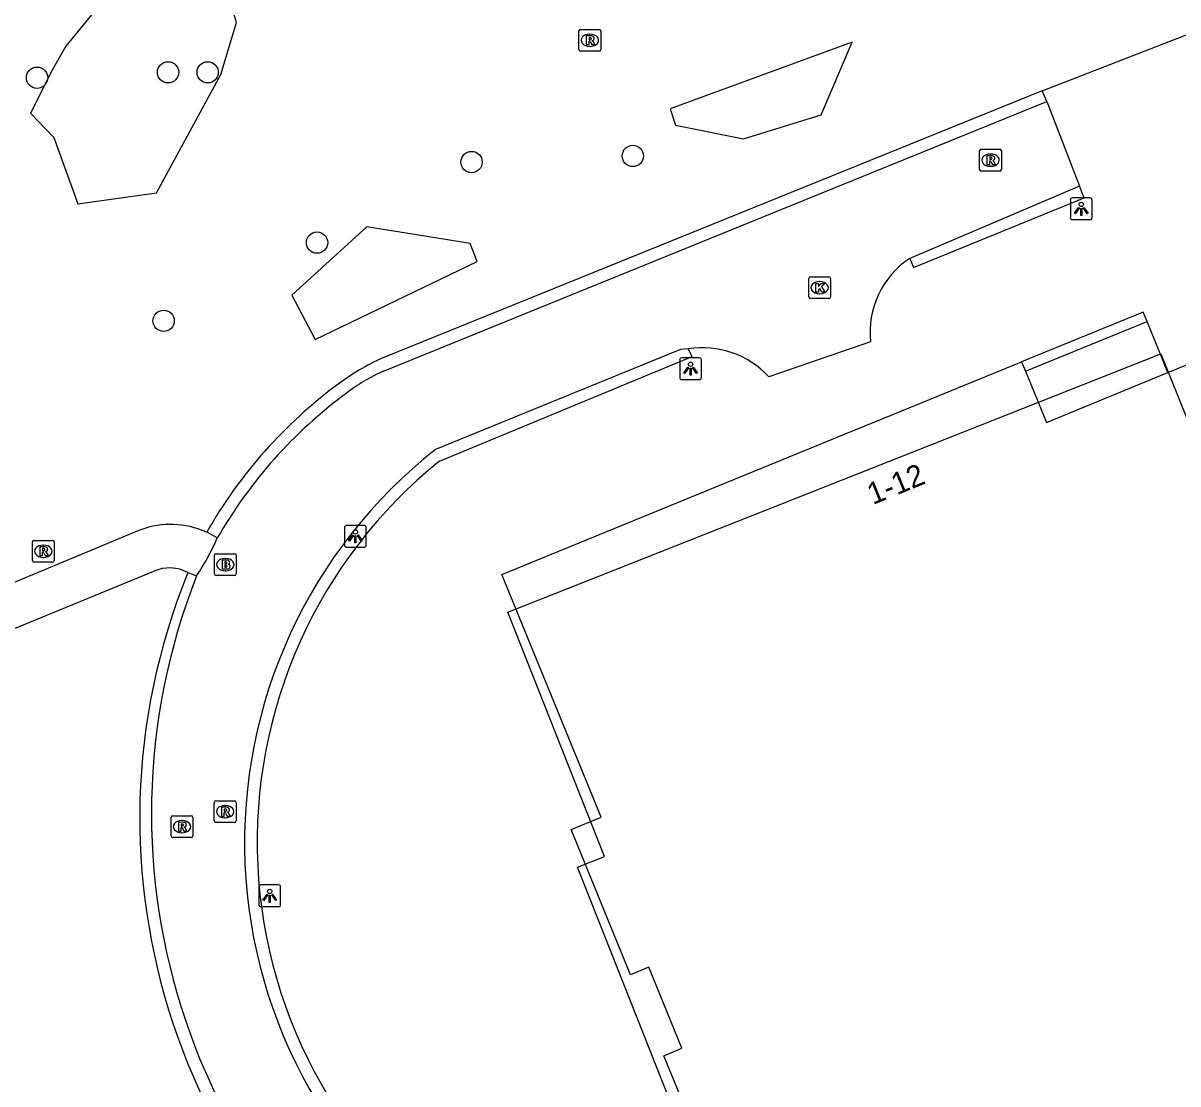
# Model space of a CAD drawing. Extents: x 156664 to 157568, y 383571 to 384421.
# Drawn here: x 156758.2 to 156811.2, y 383832.6 to 383881.2 of the extents above; entities that cross this region are included whole.
import ezdxf

# ---------------------------------------------------------------- set-up
doc = ezdxf.new("R2010")
doc.units = 0
for name, color, linetype in [('IMGEO_Boom', 7, 'Continuous'), ('IMGEO_Brandkraan', 7, 'Continuous'), ('IMGEO_Groenvoorziening', 7, 'Continuous'), ('IMGEO_Kolk', 7, 'Continuous'), ('IMGEO_Lichtpunt', 7, 'Continuous'), ('IMGEO_Muur', 7, 'Continuous'), ('IMGEO_Pand', 7, 'Continuous'), ('IMGEO_Pand_nummerreeks', 7, 'Continuous'), ('IMGEO_Pand_vergunning_verleend', 7, 'Continuous'), ('IMGEO_Rijbaan_lokaal_gesloten', 7, 'Continuous'), ('IMGEO_Rijbaan_lokaal_open', 7, 'Continuous'), ('IMGEO_Rioolput', 7, 'Continuous'), ('IMGEO_Voetpad_halfverhard', 7, 'Continuous'), ('IMGEO_Voetpad_op_trap', 7, 'Continuous')]:
    doc.layers.add(name, color=color, linetype=linetype)

msp = doc.modelspace()

# ---------------------------------------------------------------- linework, layer by layer
at = {"layer": 'IMGEO_Boom'}
for centre in [(156758.877, 383878.729), (156764.888, 383878.978), (156766.703, 383878.978), (156786.206, 383875.144), (156778.807, 383874.862), (156771.719, 383871.166), (156764.683, 383867.578)]:
    msp.add_circle(centre, 0.489, dxfattribs=at)
at = {"layer": 'IMGEO_Brandkraan'}
for p, q in [((156767.014, 383855.969), (156767.014, 383856.821)), ((156767.089, 383856.895), (156767.941, 383856.895)), ((156767.502, 383856.675), (156767.527, 383856.675)), ((156768.015, 383856.821), (156768.015, 383855.969)), ((156767.941, 383855.895), (156767.089, 383855.895)), ((156767.525, 383856.115), (156767.5, 383856.115))]:
    msp.add_line(p, q, dxfattribs=at)
for points in [[(156767.014, 383855.969), (156767.014, 383856.821)], [(156767.089, 383856.895), (156767.941, 383856.895)], [(156767.362, 383856.595), (156767.362, 383856.195), (156767.575, 383856.195)], [(156767.593, 383856.595), (156767.362, 383856.595)], [(156767.541, 383856.514), (156767.487, 383856.514), (156767.487, 383856.438)], [(156767.487, 383856.438), (156767.54, 383856.438)], [(156768.015, 383856.821), (156768.015, 383855.969)], [(156767.941, 383855.895), (156767.089, 383855.895)], [(156767.549, 383856.362), (156767.487, 383856.362), (156767.487, 383856.281)], [(156767.487, 383856.281), (156767.549, 383856.281)]]:
    msp.add_lwpolyline(points, dxfattribs=at)
for centre, radius, start, end in [((156767.091, 383856.819), 0.0765, 91.552, 178.448), ((156767.091, 383856.819), 0.0765, 91.552, 178.448), ((156767.542, 383856.476), 0.0379, 267.8285, 90.9355), ((156767.597, 383856.45), 0.145, 59.4692, 91.5367), ((156767.622, 383856.497), 0.0922, 285.5137, 58.1501), ((156767.627, 383856.305), 0.105, 301.3115, 78.989), ((156767.939, 383856.819), 0.0765, 1.552, 88.448), ((156767.939, 383856.819), 0.0765, 1.552, 88.448), ((156767.091, 383855.971), 0.0765, 181.552, 268.448), ((156767.091, 383855.971), 0.0765, 181.552, 268.448), ((156767.55, 383856.321), 0.0404, 269.8759, 90.5077), ((156767.581, 383856.446), 0.251, 268.6676, 293.5347), ((156767.939, 383855.971), 0.0765, 271.552, 358.448), ((156767.939, 383855.971), 0.0765, 271.552, 358.448)]:
    msp.add_arc(centre, radius, start, end, dxfattribs=at)
for centre, major_axis, ratio, start_param, end_param in [((156767.501, 383856.395), (-0.387, 0.002), 0.722429, 4.712389, 7.853982), ((156767.526, 383856.395), (-0.39, 0.002), 0.717154, 1.570796, 4.712389)]:
    msp.add_ellipse(centre, major_axis=major_axis, ratio=ratio, start_param=start_param, end_param=end_param, dxfattribs=at)
at = {"layer": 'IMGEO_Groenvoorziening'}
for points in [[(156767.313, 383878.874), (156768.021, 383881.267), (156767.299, 383883.721), (156765.415, 383884.973), (156763.24, 383883.907), (156760.194, 383880.185), (156759.562, 383879.076), (156758.573, 383877.099), (156759.648, 383875.982), (156760.744, 383872.951), (156764.354, 383873.446), (156767.313, 383878.874)], [(156804.978, 383878.126), (156811.831, 383880.795)], [(156787.923, 383877.302), (156788.163, 383876.561), (156791.276, 383875.93), (156794.852, 383877.022), (156796.266, 383880.363), (156787.923, 383877.302)], [(156779.059, 383870.302), (156778.739, 383871.124), (156773.998, 383871.897), (156770.569, 383868.754), (156771.64, 383866.725), (156779.059, 383870.302)]]:
    msp.add_lwpolyline(points, dxfattribs=at)
at = {"layer": 'IMGEO_Kolk'}
for p, q in [((156794.276, 383868.672), (156794.276, 383869.524)), ((156794.351, 383869.598), (156795.203, 383869.598)), ((156794.764, 383869.378), (156794.789, 383869.378)), ((156795.277, 383869.524), (156795.277, 383868.672)), ((156795.203, 383868.598), (156794.351, 383868.598)), ((156794.787, 383868.818), (156794.762, 383868.818))]:
    msp.add_line(p, q, dxfattribs=at)
for points in [[(156794.276, 383868.672), (156794.276, 383869.524)], [(156794.351, 383869.598), (156795.203, 383869.598)], [(156794.597, 383869.298), (156794.72, 383869.298), (156794.72, 383869.147), (156794.85, 383869.298), (156795.014, 383869.298), (156794.868, 383869.147), (156795.021, 383868.898), (156794.869, 383868.898), (156794.784, 383869.062), (156794.72, 383868.995), (156794.72, 383868.898), (156794.597, 383868.898), (156794.597, 383869.298)], [(156795.277, 383869.524), (156795.277, 383868.672)], [(156795.203, 383868.598), (156794.351, 383868.598)]]:
    msp.add_lwpolyline(points, dxfattribs=at)
for centre, start, end in [((156794.353, 383869.522), 91.552, 178.448), ((156794.353, 383869.522), 91.552, 178.448), ((156795.201, 383869.522), 1.552, 88.448), ((156795.201, 383869.522), 1.552, 88.448), ((156794.353, 383868.674), 181.552, 268.448), ((156794.353, 383868.674), 181.552, 268.448), ((156795.201, 383868.674), 271.552, 358.448), ((156795.201, 383868.674), 271.552, 358.448)]:
    msp.add_arc(centre, 0.0765, start, end, dxfattribs=at)
for centre, major_axis, ratio, start_param, end_param in [((156794.763, 383869.098), (-0.387, 0.002), 0.722429, 4.712389, 7.853982), ((156794.788, 383869.098), (-0.39, 0.002), 0.717154, 1.570796, 4.712389)]:
    msp.add_ellipse(centre, major_axis=major_axis, ratio=ratio, start_param=start_param, end_param=end_param, dxfattribs=at)
at = {"layer": 'IMGEO_Lichtpunt'}
for p, q in [((156806.276, 383873.12), (156806.276, 383872.313)), ((156806.276, 383873.12), (156806.276, 383872.313)), ((156807.178, 383873.215), (156806.37, 383873.215)), ((156807.178, 383873.215), (156806.37, 383873.215)), ((156807.272, 383872.313), (156807.272, 383873.12)), ((156807.272, 383872.313), (156807.272, 383873.12)), ((156806.37, 383872.219), (156807.178, 383872.219)), ((156806.37, 383872.219), (156807.178, 383872.219)), ((156788.355, 383865.785), (156788.355, 383864.978)), ((156788.355, 383865.785), (156788.355, 383864.978)), ((156789.257, 383865.88), (156788.449, 383865.88)), ((156789.257, 383865.88), (156788.449, 383865.88)), ((156789.351, 383864.978), (156789.351, 383865.785)), ((156789.351, 383864.978), (156789.351, 383865.785)), ((156788.449, 383864.884), (156789.257, 383864.884)), ((156788.449, 383864.884), (156789.257, 383864.884)), ((156772.98, 383858.094), (156772.98, 383857.287)), ((156772.98, 383858.094), (156772.98, 383857.287)), ((156773.882, 383858.189), (156773.074, 383858.189)), ((156773.882, 383858.189), (156773.074, 383858.189)), ((156773.976, 383857.287), (156773.976, 383858.094)), ((156773.976, 383857.287), (156773.976, 383858.094)), ((156773.074, 383857.193), (156773.882, 383857.193)), ((156773.074, 383857.193), (156773.882, 383857.193)), ((156769.054, 383841.606), (156769.054, 383840.799)), ((156769.054, 383841.606), (156769.054, 383840.799)), ((156769.956, 383841.701), (156769.148, 383841.701)), ((156769.956, 383841.701), (156769.148, 383841.701)), ((156770.05, 383840.799), (156770.05, 383841.606)), ((156770.05, 383840.799), (156770.05, 383841.606)), ((156769.148, 383840.705), (156769.956, 383840.705)), ((156769.148, 383840.705), (156769.956, 383840.705))]:
    msp.add_line(p, q, dxfattribs=at)
for points in [[(156806.65, 383872.784), (156806.689, 383872.756), (156806.501, 383872.494), (156806.463, 383872.521), (156806.65, 383872.784)], [(156806.752, 383872.736), (156806.799, 383872.736), (156806.799, 383872.414), (156806.752, 383872.414), (156806.752, 383872.736)], [(156806.862, 383872.756), (156806.9, 383872.783), (156807.087, 383872.521), (156807.048, 383872.493), (156806.862, 383872.756)], [(156788.729, 383865.449), (156788.768, 383865.421), (156788.58, 383865.159), (156788.542, 383865.186), (156788.729, 383865.449)], [(156788.941, 383865.421), (156788.979, 383865.448), (156789.166, 383865.186), (156789.127, 383865.158), (156788.941, 383865.421)], [(156788.831, 383865.401), (156788.878, 383865.401), (156788.878, 383865.079), (156788.831, 383865.079), (156788.831, 383865.401)], [(156773.354, 383857.758), (156773.393, 383857.73), (156773.205, 383857.468), (156773.167, 383857.495), (156773.354, 383857.758)], [(156773.456, 383857.71), (156773.503, 383857.71), (156773.503, 383857.388), (156773.456, 383857.388), (156773.456, 383857.71)], [(156773.566, 383857.73), (156773.604, 383857.757), (156773.791, 383857.495), (156773.752, 383857.467), (156773.566, 383857.73)], [(156769.428, 383841.27), (156769.467, 383841.242), (156769.279, 383840.98), (156769.241, 383841.007), (156769.428, 383841.27)], [(156769.53, 383841.222), (156769.577, 383841.222), (156769.577, 383840.9), (156769.53, 383840.9), (156769.53, 383841.222)], [(156769.64, 383841.242), (156769.678, 383841.269), (156769.865, 383841.007), (156769.826, 383840.979), (156769.64, 383841.242)]]:
    msp.add_lwpolyline(points, dxfattribs=at)
for centre in [(156806.775, 383872.918), (156788.854, 383865.583), (156773.479, 383857.892), (156769.553, 383841.404)]:
    msp.add_circle(centre, 0.0994, dxfattribs=at)
for centre, start, end in [((156806.37, 383873.12), 90, 180), ((156806.37, 383873.12), 90, 180), ((156807.178, 383873.12), 0, 90), ((156807.178, 383873.12), 0, 90), ((156806.37, 383872.313), 180, 270), ((156806.37, 383872.313), 180, 270), ((156807.178, 383872.313), 270, 0), ((156807.178, 383872.313), 270, 360), ((156788.449, 383865.785), 90, 180), ((156788.449, 383865.785), 90, 180), ((156789.257, 383865.785), 0, 90), ((156789.257, 383865.785), 0, 90), ((156788.449, 383864.978), 180, 270), ((156788.449, 383864.978), 180, 270), ((156789.257, 383864.978), 270, 0), ((156789.257, 383864.978), 270, 360), ((156773.074, 383858.094), 90, 180), ((156773.074, 383858.094), 90, 180), ((156773.882, 383858.094), 0, 90), ((156773.882, 383858.094), 0, 90), ((156773.074, 383857.287), 180, 270), ((156773.074, 383857.287), 180, 270), ((156773.882, 383857.287), 270, 0), ((156773.882, 383857.287), 270, 360), ((156769.148, 383841.606), 90, 180), ((156769.148, 383841.606), 90, 180), ((156769.956, 383841.606), 0, 90), ((156769.956, 383841.606), 0, 90), ((156769.148, 383840.799), 180, 270), ((156769.148, 383840.799), 180, 270), ((156769.956, 383840.799), 270, 0), ((156769.956, 383840.799), 270, 360)]:
    msp.add_arc(centre, 0.0946, start, end, dxfattribs=at)
at = {"layer": 'IMGEO_Muur'}
for points in [[(156809.794, 383867.543), (156809.615, 383867.977), (156804.039, 383865.696)], [(156804.217, 383865.261), (156809.794, 383867.543)]]:
    msp.add_lwpolyline(points, dxfattribs=at)
at = {"layer": 'IMGEO_Pand'}
for points in [[(156807.966, 383825.04), (156808.116, 383824.67), (156800.741, 383821.682), (156799.598, 383824.496), (156795.415, 383822.785), (156793.137, 383828.33), (156790.362, 383827.188), (156787.627, 383833.862), (156788.459, 383834.206), (156786.933, 383837.925), (156786.103, 383837.581), (156783.375, 383844.241), (156784.761, 383844.813), (156780.2, 383855.943), (156794.056, 383861.612), (156795.923, 383862.376), (156798.209, 383863.311), (156804.039, 383865.696)], [(156804.039, 383865.696), (156804.217, 383865.261)], [(156810.752, 383865.212), (156812.318, 383865.856), (156814.59, 383860.304), (156817.377, 383861.45), (156822.064, 383849.936), (156821.462, 383849.689), (156823.742, 383844.139), (156820.198, 383842.684), (156822.503, 383837.144), (156816.871, 383834.832), (156818.054, 383832.045), (156811.056, 383829.074)], [(156804.217, 383865.261), (156805.179, 383862.921), (156810.752, 383865.212)]]:
    msp.add_lwpolyline(points, dxfattribs=at)
at = {"layer": 'IMGEO_Pand_vergunning_verleend'}
msp.add_lwpolyline([(156780.469, 383854.207), (156810.422, 383866.069), (156813.706, 383857.943), (156816.747, 383859.147), (156823.563, 383841.936), (156820.432, 383840.696), (156822.305, 383835.967), (156820.454, 383835.234), (156822.799, 383829.314), (156801.042, 383820.698), (156799.834, 383823.747), (156795.744, 383822.127), (156793.475, 383827.857), (156790.011, 383826.485), (156783.663, 383842.517), (156784.904, 383843.008), (156780.469, 383854.207)], dxfattribs=at)
at = {"layer": 'IMGEO_Rijbaan_lokaal_gesloten'}
for points in [[(156804.978, 383878.126), (156774.705, 383865.868)], [(156805.203, 383877.639), (156804.978, 383878.126)], [(156774.773, 383865.272), (156805.203, 383877.639)], [(156806.698, 383873.755), (156798.908, 383870.442)], [(156798.908, 383870.442), (156799.086, 383870.018), (156806.905, 383873.221), (156806.698, 383873.755)], [(156788.751, 383866.299), (156788.39, 383866.267), (156777.151, 383861.675)], [(156777.333, 383861.139), (156788.93, 383865.945), (156788.751, 383866.299)], [(156767.144, 383857.616), (156766.659, 383857.882)], [(156765.799, 383856.03), (156766.195, 383855.876)]]:
    msp.add_lwpolyline(points, dxfattribs=at)
for centre, radius, start, end in [((156779.457, 383855.553), 11.357, 114.7348, 126.5541), ((156778.442, 383857.162), 8.902, 114.3401, 127.2638), ((156785.762, 383846.992), 21.989, 126.4662, 150.3149), ((156785.971, 383846.787), 21.719, 126.4993, 150.0922), ((156791.351, 383843.635), 22.958, 128.2084, 236.6145), ((156791.42, 383843.662), 22.447, 128.8708, 236.5377), ((156793.467, 383844.757), 29.876, 157.8328, 238.869), ((156793.864, 383844.982), 29.736, 158.5089, 238.5458)]:
    msp.add_arc(centre, radius, start, end, dxfattribs=at)
at = {"layer": 'IMGEO_Rijbaan_lokaal_open'}
for points in [[(156805.203, 383877.639), (156806.698, 383873.755)], [(156797.106, 383866.622), (156792.449, 383865.012)]]:
    msp.add_lwpolyline(points, dxfattribs=at)
for centre, radius, start, end in [((156801.172, 383867.039), 4.087, 123.636, 185.8549), ((156789.388, 383862.174), 4.174, 42.8376, 98.784), ((156755.707, 383862.725), 12.526, 326.8542, 335.9295)]:
    msp.add_arc(centre, radius, start, end, dxfattribs=at)
at = {"layer": 'IMGEO_Rioolput'}
for p, q in [((156783.736, 383880.023), (156783.736, 383880.875)), ((156783.811, 383880.949), (156784.663, 383880.949)), ((156784.737, 383880.875), (156784.737, 383880.023)), ((156784.224, 383880.729), (156784.249, 383880.729)), ((156784.663, 383879.949), (156783.811, 383879.949)), ((156784.247, 383880.169), (156784.222, 383880.169)), ((156802.115, 383874.524), (156802.115, 383875.376)), ((156802.19, 383875.45), (156803.042, 383875.45)), ((156802.603, 383875.23), (156802.628, 383875.23)), ((156803.116, 383875.376), (156803.116, 383874.524)), ((156803.042, 383874.45), (156802.19, 383874.45)), ((156802.626, 383874.67), (156802.601, 383874.67)), ((156758.74, 383857.507), (156759.592, 383857.507)), ((156758.665, 383856.581), (156758.665, 383857.433)), ((156759.153, 383857.287), (156759.178, 383857.287)), ((156759.666, 383857.433), (156759.666, 383856.581)), ((156759.592, 383856.507), (156758.74, 383856.507)), ((156759.176, 383856.727), (156759.151, 383856.727)), ((156767.006, 383844.635), (156767.006, 383845.487)), ((156767.081, 383845.561), (156767.933, 383845.561)), ((156767.494, 383845.341), (156767.519, 383845.341)), ((156768.007, 383845.487), (156768.007, 383844.635)), ((156765.024, 383843.946), (156765.024, 383844.798)), ((156765.099, 383844.872), (156765.951, 383844.872)), ((156766.025, 383844.798), (156766.025, 383843.946)), ((156767.517, 383844.781), (156767.492, 383844.781)), ((156765.512, 383844.652), (156765.537, 383844.652)), ((156767.933, 383844.561), (156767.081, 383844.561)), ((156765.951, 383843.872), (156765.099, 383843.872)), ((156765.535, 383844.092), (156765.51, 383844.092))]:
    msp.add_line(p, q, dxfattribs=at)
for points in [[(156783.736, 383880.023), (156783.736, 383880.875)], [(156783.811, 383880.949), (156784.663, 383880.949)], [(156784.737, 383880.875), (156784.737, 383880.023)], [(156784.325, 383880.647), (156784.073, 383880.649), (156784.073, 383880.249)], [(156784.073, 383880.249), (156784.197, 383880.249), (156784.197, 383880.411), (156784.208, 383880.411)], [(156784.251, 383880.568), (156784.197, 383880.568), (156784.197, 383880.487)], [(156784.197, 383880.487), (156784.249, 383880.487)], [(156784.255, 383880.382), (156784.326, 383880.249), (156784.466, 383880.249), (156784.401, 383880.375)], [(156784.663, 383879.949), (156783.811, 383879.949)], [(156802.115, 383874.524), (156802.115, 383875.376)], [(156802.19, 383875.45), (156803.042, 383875.45)], [(156802.704, 383875.148), (156802.452, 383875.15), (156802.452, 383874.75)], [(156802.63, 383875.069), (156802.576, 383875.069), (156802.576, 383874.988)], [(156802.576, 383874.988), (156802.628, 383874.988)], [(156803.116, 383875.376), (156803.116, 383874.524)], [(156803.042, 383874.45), (156802.19, 383874.45)], [(156802.452, 383874.75), (156802.576, 383874.75), (156802.576, 383874.912), (156802.587, 383874.912)], [(156802.634, 383874.883), (156802.705, 383874.75), (156802.845, 383874.75), (156802.78, 383874.876)], [(156758.74, 383857.507), (156759.592, 383857.507)], [(156758.665, 383856.581), (156758.665, 383857.433)], [(156759.254, 383857.205), (156759.002, 383857.207), (156759.002, 383856.807)], [(156759.002, 383856.807), (156759.126, 383856.807), (156759.126, 383856.969), (156759.137, 383856.969)], [(156759.18, 383857.126), (156759.126, 383857.126), (156759.126, 383857.045)], [(156759.126, 383857.045), (156759.178, 383857.045)], [(156759.184, 383856.94), (156759.255, 383856.807), (156759.395, 383856.807), (156759.33, 383856.933)], [(156759.666, 383857.433), (156759.666, 383856.581)], [(156759.592, 383856.507), (156758.74, 383856.507)], [(156767.006, 383844.635), (156767.006, 383845.487)], [(156767.081, 383845.561), (156767.933, 383845.561)], [(156768.007, 383845.487), (156768.007, 383844.635)], [(156765.024, 383843.946), (156765.024, 383844.798)], [(156765.099, 383844.872), (156765.951, 383844.872)], [(156766.025, 383844.798), (156766.025, 383843.946)], [(156767.595, 383845.259), (156767.343, 383845.261), (156767.343, 383844.861)], [(156767.343, 383844.861), (156767.467, 383844.861), (156767.467, 383845.023), (156767.478, 383845.023)], [(156767.521, 383845.18), (156767.467, 383845.18), (156767.467, 383845.099)], [(156767.467, 383845.099), (156767.519, 383845.099)], [(156767.525, 383844.994), (156767.596, 383844.861), (156767.736, 383844.861), (156767.671, 383844.987)], [(156765.613, 383844.57), (156765.361, 383844.572), (156765.361, 383844.172)], [(156765.361, 383844.172), (156765.485, 383844.172), (156765.485, 383844.334), (156765.496, 383844.334)], [(156765.539, 383844.491), (156765.485, 383844.491), (156765.485, 383844.41)], [(156765.485, 383844.41), (156765.537, 383844.41)], [(156765.543, 383844.305), (156765.614, 383844.172), (156765.754, 383844.172), (156765.689, 383844.298)], [(156767.933, 383844.561), (156767.081, 383844.561)], [(156765.951, 383843.872), (156765.099, 383843.872)]]:
    msp.add_lwpolyline(points, dxfattribs=at)
for centre, radius, start, end in [((156783.813, 383880.873), 0.0765, 91.552, 178.448), ((156783.813, 383880.873), 0.0765, 91.552, 178.448), ((156784.661, 383880.873), 0.0765, 1.552, 88.448), ((156784.661, 383880.873), 0.0765, 1.552, 88.448), ((156784.207, 383880.358), 0.0533, 26.0293, 88.6989), ((156784.233, 383880.676), 0.19, 274.7715, 282.9687), ((156784.257, 383880.472), 0.0964, 77.0061, 93.1865), ((156784.271, 383880.529), 0.0378, 276.6634, 79.6772), ((156784.324, 383880.537), 0.109, 350.3612, 89.416), ((156784.322, 383880.537), 0.112, 277.5842, 350.9817), ((156784.306, 383880.322), 0.108, 29.5134, 73.7905), ((156783.813, 383880.025), 0.0765, 181.552, 268.448), ((156783.813, 383880.025), 0.0765, 181.552, 268.448), ((156784.661, 383880.025), 0.0765, 271.552, 358.448), ((156784.661, 383880.025), 0.0765, 271.552, 358.448), ((156802.192, 383875.374), 0.0765, 91.552, 178.448), ((156802.192, 383875.374), 0.0765, 91.552, 178.448), ((156802.612, 383875.177), 0.19, 274.7715, 282.9687), ((156802.636, 383874.973), 0.0964, 77.0061, 93.1865), ((156802.65, 383875.03), 0.0378, 276.6634, 79.6772), ((156802.703, 383875.038), 0.109, 350.3612, 89.416), ((156802.701, 383875.038), 0.112, 277.5842, 350.9817), ((156803.04, 383875.374), 0.0765, 1.552, 88.448), ((156803.04, 383875.374), 0.0765, 1.552, 88.448), ((156802.192, 383874.526), 0.0765, 181.552, 268.448), ((156802.192, 383874.526), 0.0765, 181.552, 268.448), ((156802.586, 383874.859), 0.0533, 26.0293, 88.6989), ((156802.685, 383874.823), 0.108, 29.5134, 73.7905), ((156803.04, 383874.526), 0.0765, 271.552, 358.448), ((156803.04, 383874.526), 0.0765, 271.552, 358.448), ((156758.742, 383857.431), 0.0765, 91.552, 178.448), ((156758.742, 383857.431), 0.0765, 91.552, 178.448), ((156759.59, 383857.431), 0.0765, 1.552, 88.448), ((156759.59, 383857.431), 0.0765, 1.552, 88.448), ((156759.136, 383856.916), 0.0533, 26.0293, 88.6989), ((156759.162, 383857.234), 0.19, 274.7715, 282.9687), ((156759.186, 383857.03), 0.0964, 77.0061, 93.1865), ((156759.2, 383857.087), 0.0378, 276.6634, 79.6772), ((156759.253, 383857.095), 0.109, 350.3612, 89.416), ((156759.251, 383857.095), 0.112, 277.5842, 350.9817), ((156759.235, 383856.88), 0.108, 29.5134, 73.7905), ((156758.742, 383856.583), 0.0765, 181.552, 268.448), ((156758.742, 383856.583), 0.0765, 181.552, 268.448), ((156759.59, 383856.583), 0.0765, 271.552, 358.448), ((156759.59, 383856.583), 0.0765, 271.552, 358.448), ((156767.083, 383845.485), 0.0765, 91.552, 178.448), ((156767.083, 383845.485), 0.0765, 91.552, 178.448), ((156767.931, 383845.485), 0.0765, 1.552, 88.448), ((156767.931, 383845.485), 0.0765, 1.552, 88.448), ((156765.101, 383844.796), 0.0765, 91.552, 178.448), ((156765.101, 383844.796), 0.0765, 91.552, 178.448), ((156765.949, 383844.796), 0.0765, 1.552, 88.448), ((156765.949, 383844.796), 0.0765, 1.552, 88.448), ((156767.477, 383844.97), 0.0533, 26.0293, 88.6989), ((156767.503, 383845.288), 0.19, 274.7715, 282.9687), ((156767.527, 383845.084), 0.0964, 77.0061, 93.1865), ((156767.541, 383845.141), 0.0378, 276.6634, 79.6772), ((156767.594, 383845.149), 0.109, 350.3612, 89.416), ((156767.592, 383845.149), 0.112, 277.5842, 350.9817), ((156767.576, 383844.934), 0.108, 29.5134, 73.7905), ((156765.495, 383844.281), 0.0533, 26.0293, 88.6989), ((156765.521, 383844.599), 0.19, 274.7715, 282.9687), ((156765.545, 383844.395), 0.0964, 77.0061, 93.1865), ((156765.559, 383844.452), 0.0378, 276.6634, 79.6772), ((156765.612, 383844.46), 0.109, 350.3612, 89.416), ((156765.61, 383844.46), 0.112, 277.5842, 350.9817), ((156765.594, 383844.245), 0.108, 29.5134, 73.7905), ((156767.083, 383844.637), 0.0765, 181.552, 268.448), ((156767.083, 383844.637), 0.0765, 181.552, 268.448), ((156767.931, 383844.637), 0.0765, 271.552, 358.448), ((156767.931, 383844.637), 0.0765, 271.552, 358.448), ((156765.101, 383843.948), 0.0765, 181.552, 268.448), ((156765.101, 383843.948), 0.0765, 181.552, 268.448), ((156765.949, 383843.948), 0.0765, 271.552, 358.448), ((156765.949, 383843.948), 0.0765, 271.552, 358.448)]:
    msp.add_arc(centre, radius, start, end, dxfattribs=at)
for centre, major_axis, ratio, start_param, end_param in [((156784.223, 383880.449), (-0.387, 0.002), 0.722429, 4.712389, 7.853982), ((156784.248, 383880.449), (-0.39, 0.002), 0.717154, 1.570796, 4.712389), ((156802.602, 383874.95), (-0.387, 0.002), 0.722429, 4.712389, 7.853982), ((156802.627, 383874.95), (-0.39, 0.002), 0.717154, 1.570796, 4.712389), ((156759.152, 383857.007), (-0.387, 0.002), 0.722429, 4.712389, 7.853982), ((156759.177, 383857.007), (-0.39, 0.002), 0.717154, 1.570796, 4.712389), ((156767.493, 383845.061), (-0.387, 0.002), 0.722429, 4.712389, 7.853982), ((156767.518, 383845.061), (-0.39, 0.002), 0.717154, 1.570796, 4.712389), ((156765.511, 383844.372), (-0.387, 0.002), 0.722429, 4.712389, 7.853982), ((156765.536, 383844.372), (-0.39, 0.002), 0.717154, 1.570796, 4.712389)]:
    msp.add_ellipse(centre, major_axis=major_axis, ratio=ratio, start_param=start_param, end_param=end_param, dxfattribs=at)
at = {"layer": 'IMGEO_Voetpad_halfverhard'}
for points in [[(156763.462, 383857.925), (156745.823, 383850.568)], [(156766.659, 383857.882), (156766.445, 383857.964)], [(156746.53, 383848.809), (156764.227, 383856.088)]]:
    msp.add_lwpolyline(points, dxfattribs=at)
for centre, radius, start, end in [((156765.001, 383854.285), 3.952, 68.5726, 112.9255), ((156764.953, 383854.439), 1.801, 61.999, 113.775)]:
    msp.add_arc(centre, radius, start, end, dxfattribs=at)
at = {"layer": 'IMGEO_Voetpad_op_trap'}
msp.add_lwpolyline([(156810.752, 383865.212), (156809.794, 383867.543)], dxfattribs=at)

# ---------------------------------------------------------------- texts
at = {"layer": 'IMGEO_Pand_nummerreeks'}
msp.add_text('1-12', height=1, rotation=22.2537, dxfattribs=at).set_placement((156797.216, 383859.123))

doc.saveas('drawing.dxf')
